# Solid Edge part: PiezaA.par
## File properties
Author: ADI
Template: Normal.par
Last saved by: ADI
Revision: 1
Application: Solid Edge
Densidad: 0 kg/mm^3
Precisión: 0,99
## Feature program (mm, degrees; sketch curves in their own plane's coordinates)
sketch for "unnamed Protrusion 1" plane through (0, 0, 0) normal (0, 0, 1) x-axis (1, 0, 0)
  line (-33.9728, 0) -> (196.0272, 0)
  line (196.0272, 0) -> (196.0272, 175)
  line (196.0272, 175) -> (-33.9728, 175)
  line (-33.9728, 175) -> (-33.9728, 0)
extrude "unnamed Protrusion 1" add finite 3 along +normal
sketch for "VaciadoExtruido_1" plane through (81.0272, 87.5, 3) normal (0, 0, 1) x-axis (0, 1, 0)
  line (-62.5, -80) -> (87.5, -80)
  line (87.5, -80) -> (87.5, 80)
  line (87.5, 80) -> (-62.5, 80)
  arc centre (-62.5, 70) radius 10 from (-62.5, 80) to (-72.5, 70) ccw
  line (-72.5, 70) -> (-72.5, -70)
  arc centre (-62.5, -70) radius 10 from (-72.5, -70) to (-62.5, -80) ccw
extrude "VaciadoExtruido_1" cut finite 3 along -normal
sketch for "VaciadoExtruido_2" plane through (81.0272, 87.5, 3) normal (0, 0, 1) x-axis (0, 1, 0)
  line (87.5, -115) -> (-87.5, -95)
  line (-87.5, -95) -> (-87.5, -115)
  line (-87.5, -115) -> (87.5, -115)
extrude "VaciadoExtruido_2" cut finite 3 along -normal
sketch for "VaciadoExtruido_3" plane through (81.0272, 87.5, 3) normal (0, 0, 1) x-axis (0, 1, 0)
  line (87.5, 115) -> (-87.5, 95)
  line (-87.5, 95) -> (-87.5, 115)
  line (-87.5, 115) -> (87.5, 115)
extrude "VaciadoExtruido_3" cut finite 66.675 along -normal
sketch for "VaciadoExtruido_4" plane through (81.0272, 87.5, 3) normal (0, 0, 1) x-axis (0, 1, 0)
  line (-62.5, 80) -> (87.5, 100)
  line (87.5, 100) -> (87.5, 80)
  line (87.5, 80) -> (-62.5, 80)
extrude "VaciadoExtruido_4" cut finite 3 along -normal
sketch for "VaciadoExtruido_5" plane through (81.0272, 87.5, 3) normal (0, 0, 1) x-axis (0, 1, 0)
  line (87.5, -97.5) -> (-62.5, -80)
  line (-62.5, -80) -> (87.5, -80)
  line (87.5, -80) -> (87.5, -97.5)
extrude "VaciadoExtruido_5" cut finite 3 along -normal
sketch for "VaciadoExtruido_6" plane through (81.0272, 87.5, 3) normal (0, 0, 1) x-axis (-1, 0, 0)
  line (-94.9619, 87.8333) -> (-95.7227, 81.1766)
  line (-95.7227, 81.1766) -> (-92.7421, 80.836)
  line (-92.7421, 80.836) -> (-91.9813, 87.4926)
  line (-91.9813, 87.4926) -> (-94.9619, 87.8333)
extrude "VaciadoExtruido_6" cut finite 3 along -normal
sketch for "VaciadoExtruido_7" plane through (81.0272, 87.5, 3) normal (0, 0, 1) x-axis (-1, 0, 0)
  line (94.968, 87.7798) -> (95.7288, 81.1231)
  line (95.7288, 81.1231) -> (93.0035, 80.8116)
  line (93.0035, 80.8116) -> (92.2428, 87.4683)
  line (92.2428, 87.4683) -> (94.968, 87.7798)
extrude "VaciadoExtruido_7" cut finite 3 along -normal
sketch for "VaciadoExtruido_8" plane through (81.0272, 87.5, 3) normal (0, 0, 1) x-axis (-1, 0, 0)
  line (-101.8518, 27.5465) -> (-102.6183, 20.8402)
  line (-102.6183, 20.8402) -> (-99.6377, 20.4996)
  line (-99.6377, 20.4996) -> (-98.8712, 27.2059)
  line (-98.8712, 27.2059) -> (-101.8518, 27.5465)
extrude "VaciadoExtruido_8" cut finite 3 along -normal
sketch for "VaciadoExtruido_10" plane through (81.0272, 87.5, 3) normal (0, 0, 1) x-axis (-1, 0, 0)
  line (101.8603, 27.4725) -> (102.6551, 20.5178)
  line (102.6551, 20.5178) -> (99.6745, 20.1771)
  line (99.6745, 20.1771) -> (98.8797, 27.1318)
  line (98.8797, 27.1318) -> (101.8603, 27.4725)
extrude "VaciadoExtruido_10" cut finite 3 along -normal
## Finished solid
Body 1: solid body, 26 faces, 72 edges, 48 vertices.
  Faces by surface: plane 24, cylinder 2
  Edges by curve: line 68, circle 4
Bounding box of the edges (mm): 230.000 x 175.000 x 3.000, from (-33.9728, 0, 0) to (196.0272, 175, 3).
Cylindrical faces by radius (mm): R10 x2
Planar faces by outward normal: +y 3, +z 1, -y 1, -z 1, oblique 18
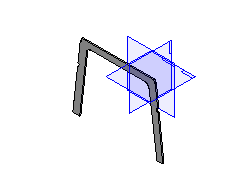
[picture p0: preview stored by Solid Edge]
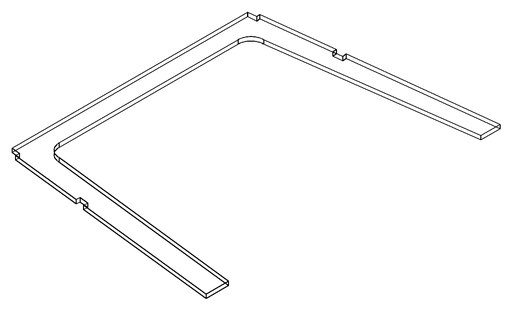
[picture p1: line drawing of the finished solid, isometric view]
